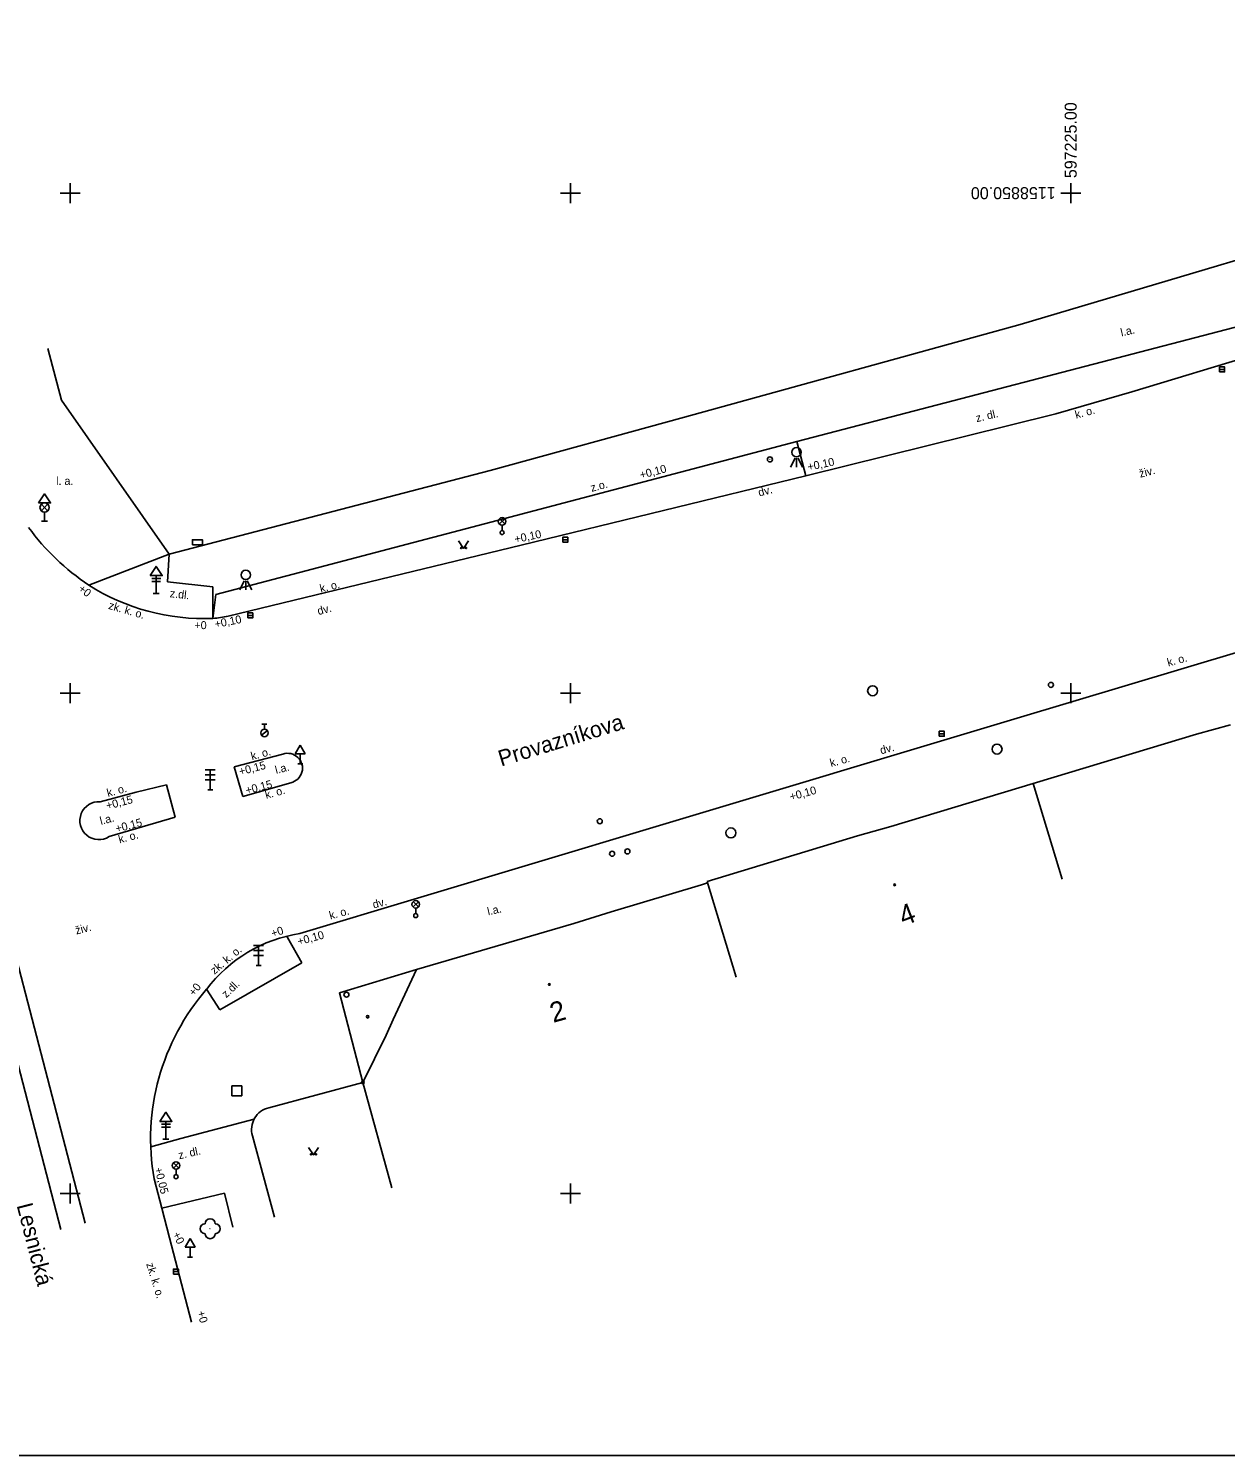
# Model space of a CAD drawing. Extents: x -597333 to -596488, y -1158921 to -1158644.
# Drawn here: x -597277.1 to -597217.3, y -1158913.1 to -1158841.8 of the extents above; entities that cross this region are included whole.
import ezdxf

# ---------------------------------------------------------------- set-up
doc = ezdxf.new("R2010")
doc.units = 0
for name, color, linetype in [('Vrstva 1', 7, 'Continuous'), ('Vrstva 10', 7, 'Continuous'), ('Vrstva 14', 7, 'Continuous'), ('Vrstva 15', 7, 'Continuous'), ('Vrstva 19', 7, 'Continuous'), ('Vrstva 23', 7, 'Continuous'), ('Vrstva 24', 7, 'Continuous'), ('Vrstva 25', 7, 'Continuous'), ('Vrstva 26', 7, 'Continuous'), ('Vrstva 29', 7, 'Continuous'), ('Vrstva 4', 7, 'Continuous'), ('Vrstva 42', 7, 'Continuous'), ('Vrstva 43', 7, 'Continuous'), ('Vrstva 44', 7, 'Continuous'), ('Vrstva 49', 7, 'Continuous'), ('Vrstva 5', 7, 'Continuous'), ('Vrstva 50', 7, 'Continuous'), ('Vrstva 52', 7, 'Continuous'), ('Vrstva 62', 7, 'Continuous'), ('Vrstva 7', 7, 'Continuous')]:
    doc.layers.add(name, color=color, linetype=linetype)

msp = doc.modelspace()

# ---------------------------------------------------------------- linework, layer by layer
at = {"layer": 'Vrstva 1'}
msp.add_lwpolyline([(-597328.148, -1158764.603), (-597328.148, -1158913.103), (-597118.148, -1158913.103), (-597118.148, -1158764.603)], close=True, dxfattribs=at)
at = {"layer": 'Vrstva 10'}
for p, q in [((-597276.111, -1158857.77), (-597275.433, -1158860.345)), ((-597275.433, -1158860.345), (-597270.051, -1158868.049)), ((-597270.051, -1158868.049), (-597254.01, -1158863.867)), ((-597260.372, -1158894.457), (-597265.078, -1158895.721)), ((-597265.889, -1158897.126), (-597264.792, -1158901.192))]:
    msp.add_line(p, q, dxfattribs=at)
for points in [[(-597227.519, -1158856.574), (-597207.014, -1158850.47), (-597187.728, -1158844.729)], [(-597254.01, -1158863.867), (-597244.293, -1158861.192), (-597227.519, -1158856.574)]]:
    msp.add_lwpolyline(points, dxfattribs=at)
msp.add_arc((-597264.82, -1158896.806), 1.116, 103.36333, 196.64751, dxfattribs=at)
at = {"layer": 'Vrstva 14'}
for points in [[(-597255.588, -1158867.388), (-597255.338, -1158867.763), (-597255.088, -1158867.388)], [(-597263.091, -1158897.7), (-597262.841, -1158898.075), (-597262.591, -1158897.7)]]:
    msp.add_lwpolyline(points, dxfattribs=at)
for centre, radius in [((-597255.463, -1158867.738), 0.025), ((-597255.213, -1158867.738), 0.025), ((-597262.966, -1158898.05), 0.025), ((-597262.716, -1158898.05), 0.025), ((-597268.006, -1158901.768), 0.00025)]:
    msp.add_circle(centre, radius, dxfattribs=at)
for centre, start, end in [((-597268.006, -1158901.518), 0, 179.99999), ((-597268.256, -1158901.768), 89.99999, 269.99999), ((-597268.006, -1158902.018), 179.99999, 359.99999), ((-597267.756, -1158901.768), 270, 89.99999)]:
    msp.add_arc(centre, 0.25, start, end, dxfattribs=at)
at = {"layer": 'Vrstva 15'}
for centre, radius in [((-597240.029, -1158863.311), 0.125), ((-597240.029, -1158863.311), 0.00025), ((-597233.796, -1158884.579), 0.0438), ((-597251.054, -1158889.555), 0.0438), ((-597260.136, -1158891.173), 0.0625), ((-597260.136, -1158891.173), 0.0625), ((-597260.372, -1158894.457), 0.0625), ((-597260.372, -1158894.457), 0.0625)]:
    msp.add_circle(centre, radius, dxfattribs=at)
at = {"layer": 'Vrstva 19'}
for p, q in [((-597275.466, -1158901.802), (-597286.662, -1158858.767)), ((-597263.503, -1158877.595), (-597263.753, -1158878.028)), ((-597263.503, -1158877.595), (-597263.253, -1158878.028)), ((-597263.753, -1158878.028), (-597263.253, -1158878.028)), ((-597263.503, -1158878.528), (-597263.503, -1158878.028)), ((-597267.753, -1158878.825), (-597268.253, -1158878.825)), ((-597268.253, -1158879.075), (-597267.753, -1158879.075)), ((-597268.003, -1158879.825), (-597268.003, -1158878.825)), ((-597263.628, -1158878.528), (-597263.378, -1158878.528)), ((-597268.253, -1158879.325), (-597267.753, -1158879.325)), ((-597268.128, -1158879.825), (-597267.878, -1158879.825)), ((-597265.339, -1158887.604), (-597265.839, -1158887.604)), ((-597265.589, -1158888.604), (-597265.589, -1158887.604)), ((-597265.839, -1158887.854), (-597265.339, -1158887.854)), ((-597265.839, -1158888.104), (-597265.339, -1158888.104)), ((-597265.714, -1158888.604), (-597265.464, -1158888.604)), ((-597269.008, -1158902.262), (-597269.258, -1158902.695)), ((-597269.258, -1158902.695), (-597268.758, -1158902.695)), ((-597269.008, -1158902.262), (-597268.758, -1158902.695)), ((-597269.008, -1158903.195), (-597269.008, -1158902.695)), ((-597269.133, -1158903.195), (-597268.883, -1158903.195))]:
    msp.add_line(p, q, dxfattribs=at)
at = {"layer": 'Vrstva 23'}
for p, q in [((-597266.419, -1158894.622), (-597266.919, -1158894.622)), ((-597266.919, -1158894.622), (-597266.919, -1158895.122)), ((-597266.419, -1158895.122), (-597266.419, -1158894.622)), ((-597266.919, -1158895.122), (-597266.419, -1158895.122))]:
    msp.add_line(p, q, dxfattribs=at)
msp.add_circle((-597261.194, -1158890.067), 0.125, dxfattribs=at)
at = {"layer": 'Vrstva 24'}
for p, q in [((-597265.438, -1158877.101), (-597265.143, -1158876.869)), ((-597265.416, -1158876.547), (-597265.166, -1158876.547)), ((-597265.291, -1158876.797), (-597265.291, -1158876.547))]:
    msp.add_line(p, q, dxfattribs=at)
for centre, radius in [((-597225.986, -1158874.582), 0.125), ((-597265.291, -1158876.985), 0.188), ((-597248.533, -1158881.4), 0.125)]:
    msp.add_circle(centre, radius, dxfattribs=at)
at = {"layer": 'Vrstva 25'}
for p, q in [((-597217.561, -1158858.815), (-597217.311, -1158858.815)), ((-597250.386, -1158867.327), (-597250.137, -1158867.326)), ((-597266.123, -1158871.111), (-597265.873, -1158871.111)), ((-597231.567, -1158877.028), (-597231.317, -1158877.028)), ((-597269.839, -1158903.911), (-597269.589, -1158903.911))]:
    msp.add_line(p, q, dxfattribs=at)
for points in [[(-597217.561, -1158858.94), (-597217.311, -1158858.94), (-597217.311, -1158858.69), (-597217.561, -1158858.69)], [(-597250.386, -1158867.453), (-597250.136, -1158867.452), (-597250.137, -1158867.201), (-597250.387, -1158867.202)], [(-597266.123, -1158871.236), (-597265.873, -1158871.236), (-597265.873, -1158870.986), (-597266.123, -1158870.986)], [(-597231.567, -1158877.153), (-597231.317, -1158877.153), (-597231.317, -1158876.903), (-597231.567, -1158876.903)], [(-597269.839, -1158904.036), (-597269.589, -1158904.036), (-597269.589, -1158903.786), (-597269.839, -1158903.786)]]:
    msp.add_lwpolyline(points, close=True, dxfattribs=at)
for centre in [(-597234.897, -1158874.875), (-597228.681, -1158877.793), (-597241.98, -1158881.983)]:
    msp.add_circle(centre, 0.25, dxfattribs=at)
at = {"layer": 'Vrstva 26'}
for centre in [(-597247.915, -1158883.022), (-597247.155, -1158882.907)]:
    msp.add_circle(centre, 0.125, dxfattribs=at)
at = {"layer": 'Vrstva 29'}
for p, q in [((-597253.548, -1158866.537), (-597253.284, -1158866.273)), ((-597253.28, -1158866.536), (-597253.544, -1158866.271)), ((-597253.416, -1158866.868), (-597253.416, -1158866.593)), ((-597257.863, -1158885.684), (-597257.599, -1158885.42)), ((-597257.595, -1158885.683), (-597257.859, -1158885.418)), ((-597257.731, -1158886.015), (-597257.731, -1158885.74)), ((-597269.844, -1158898.739), (-597269.58, -1158898.475)), ((-597269.576, -1158898.738), (-597269.84, -1158898.473)), ((-597269.712, -1158899.07), (-597269.712, -1158898.795))]:
    msp.add_line(p, q, dxfattribs=at)
msp.add_lwpolyline([(-597268.889, -1158867.574), (-597268.389, -1158867.574), (-597268.389, -1158867.324), (-597268.889, -1158867.324)], close=True, dxfattribs=at)
for centre, radius in [((-597253.416, -1158866.406), 0.188), ((-597253.416, -1158866.968), 0.1), ((-597257.731, -1158885.552), 0.188), ((-597257.731, -1158886.115), 0.1), ((-597269.712, -1158898.607), 0.188), ((-597269.712, -1158899.17), 0.1)]:
    msp.add_circle(centre, radius, dxfattribs=at)
at = {"layer": 'Vrstva 4'}
for p, q in [((-597233.98, -1158881.656), (-597218.708, -1158877.038)), ((-597225.433, -1158884.295), (-597226.881, -1158879.509)), ((-597243.166, -1158884.417), (-597235.651, -1158882.131)), ((-597247.96, -1158885.926), (-597243.454, -1158884.577)), ((-597243.145, -1158884.485), (-597243.454, -1158884.577)), ((-597241.711, -1158889.201), (-597243.166, -1158884.417)), ((-597257.696, -1158888.817), (-597249.835, -1158886.508)), ((-597258.854, -1158891.311), (-597257.696, -1158888.817)), ((-597260.372, -1158894.457), (-597259.213, -1158892.094)), ((-597260.372, -1158894.457), (-597258.931, -1158899.728))]:
    msp.add_line(p, q, dxfattribs=at)
msp.add_lwpolyline([(-597257.696, -1158888.817), (-597261.543, -1158889.968), (-597260.372, -1158894.457)], dxfattribs=at)
at = {"layer": 'Vrstva 44'}
for p, q in [((-597238.776, -1158863.242), (-597239.002, -1158863.694)), ((-597238.702, -1158863.244), (-597238.702, -1158863.694)), ((-597238.627, -1158863.242), (-597238.402, -1158863.694)), ((-597276.132, -1158865.542), (-597276.432, -1158865.886)), ((-597276.432, -1158865.542), (-597276.132, -1158865.886)), ((-597276.282, -1158866.392), (-597276.282, -1158865.942)), ((-597276.432, -1158866.392), (-597276.132, -1158866.392)), ((-597270.704, -1158869.113), (-597270.704, -1158870.013)), ((-597270.924, -1158869.263), (-597270.476, -1158869.263)), ((-597270.924, -1158869.413), (-597270.481, -1158869.413)), ((-597266.298, -1158869.379), (-597266.524, -1158869.831)), ((-597266.224, -1158869.381), (-597266.224, -1158869.831)), ((-597266.149, -1158869.379), (-597265.924, -1158869.831)), ((-597270.854, -1158870.013), (-597270.554, -1158870.013)), ((-597270.433, -1158896.549), (-597269.985, -1158896.549)), ((-597270.433, -1158896.699), (-597269.99, -1158896.699)), ((-597270.213, -1158896.399), (-597270.213, -1158897.299)), ((-597270.363, -1158897.299), (-597270.063, -1158897.299))]:
    msp.add_line(p, q, dxfattribs=at)
msp.add_lwpolyline([(-597276.582, -1158865.486), (-597275.982, -1158865.486), (-597276.282, -1158865.036), (-597276.582, -1158865.486)], dxfattribs=at)
for points in [[(-597271.004, -1158869.118), (-597270.704, -1158868.663), (-597270.404, -1158869.118)], [(-597270.513, -1158896.404), (-597270.213, -1158895.949), (-597269.913, -1158896.404)]]:
    msp.add_lwpolyline(points, close=True, dxfattribs=at)
for centre, radius in [((-597238.702, -1158862.949), 0.234), ((-597276.282, -1158865.714), 0.228), ((-597266.224, -1158869.086), 0.234)]:
    msp.add_circle(centre, radius, dxfattribs=at)
at = {"layer": 'Vrstva 5'}
for p, q in [((-597218.708, -1158877.038), (-597217.007, -1158876.583)), ((-597235.651, -1158882.131), (-597233.98, -1158881.656)), ((-597249.835, -1158886.508), (-597247.96, -1158885.926)), ((-597259.213, -1158892.094), (-597258.854, -1158891.311))]:
    msp.add_line(p, q, dxfattribs=at)
at = {"layer": 'Vrstva 62'}
for p, q in [((-597275, -1158849.5), (-597275, -1158850.5)), ((-597250, -1158849.5), (-597250, -1158850.5)), ((-597225, -1158849.5), (-597225, -1158850.5)), ((-597275.5, -1158850), (-597274.5, -1158850)), ((-597250.5, -1158850), (-597249.5, -1158850)), ((-597225.5, -1158850), (-597224.5, -1158850)), ((-597275, -1158874.5), (-597275, -1158875.5)), ((-597250, -1158874.5), (-597250, -1158875.5)), ((-597225, -1158874.5), (-597225, -1158875.5)), ((-597275.5, -1158875), (-597274.5, -1158875)), ((-597250.5, -1158875), (-597249.5, -1158875)), ((-597225.5, -1158875), (-597224.5, -1158875)), ((-597275, -1158899.5), (-597275, -1158900.5)), ((-597250, -1158899.5), (-597250, -1158900.5)), ((-597275.5, -1158900), (-597274.5, -1158900)), ((-597250.5, -1158900), (-597249.5, -1158900))]:
    msp.add_line(p, q, dxfattribs=at)
at = {"layer": 'Vrstva 7'}
for p, q in [((-597221.951, -1158859.927), (-597201.328, -1158853.717)), ((-597238.686, -1158862.421), (-597216.443, -1158856.62)), ((-597274.256, -1158901.487), (-597285.452, -1158858.452)), ((-597225.739, -1158861.027), (-597221.951, -1158859.927)), ((-597228.084, -1158861.62), (-597225.739, -1158861.027)), ((-597238.243, -1158864.124), (-597228.084, -1158861.62)), ((-597253.35, -1158866.285), (-597238.686, -1158862.421)), ((-597238.243, -1158864.124), (-597238.686, -1158862.421)), ((-597252.455, -1158867.597), (-597238.243, -1158864.124)), ((-597267.724, -1158870.062), (-597253.35, -1158866.285)), ((-597267.11, -1158871.153), (-597252.455, -1158867.597)), ((-597274.069, -1158869.593), (-597270.051, -1158868.049)), ((-597270.132, -1158869.425), (-597270.051, -1158868.049)), ((-597270.132, -1158869.425), (-597267.878, -1158869.678)), ((-597267.878, -1158869.678), (-597267.868, -1158871.261)), ((-597267.868, -1158871.261), (-597267.724, -1158870.062)), ((-597266.808, -1158878.672), (-597264.37, -1158878.039)), ((-597266.808, -1158878.672), (-597266.377, -1158880.162)), ((-597270.182, -1158879.58), (-597271.701, -1158879.946)), ((-597270.182, -1158879.58), (-597269.759, -1158881.188)), ((-597266.377, -1158880.162), (-597263.978, -1158879.472)), ((-597273.504, -1158880.421), (-597271.701, -1158879.946)), ((-597269.759, -1158881.188), (-597273.055, -1158882.167)), ((-597264.175, -1158887.146), (-597264.139, -1158887.211)), ((-597263.428, -1158888.48), (-597264.139, -1158887.211)), ((-597267.518, -1158890.825), (-597263.428, -1158888.48)), ((-597268.186, -1158889.801), (-597267.518, -1158890.825)), ((-597265.808, -1158896.288), (-597269.466, -1158897.266)), ((-597270.976, -1158897.669), (-597269.466, -1158897.266)), ((-597270.426, -1158900.741), (-597270.809, -1158899.275)), ((-597270.426, -1158900.741), (-597267.287, -1158899.986)), ((-597267.287, -1158899.986), (-597266.868, -1158901.685)), ((-597270.045, -1158902.227), (-597270.426, -1158900.741)), ((-597268.941, -1158906.441), (-597270.045, -1158902.227))]:
    msp.add_line(p, q, dxfattribs=at)
msp.add_lwpolyline([(-597263.524, -1158887.016), (-597245.881, -1158881.719), (-597227.838, -1158876.302), (-597210.813, -1158871.191), (-597207.322, -1158870.143), (-597204.14, -1158869.11)], dxfattribs=at)
for centre, radius, start, end in [((-597267.49, -1158859.706), 11.876, 216.12799, 236.35866), ((-597268.317, -1158860.57), 10.7, 237.48348, 272.40539), ((-597268.767, -1158862.241), 9.065, 275.68849, 280.52938), ((-597264.136, -1158878.745), 0.744, 282.29044, 108.30774), ((-597273.567, -1158881.368), 0.949, 86.20281, 302.6405), ((-597262.448, -1158894.113), 7.178, 98.62559, 143.08118), ((-597259.546, -1158897.293), 11.436, 139.07067, 189.97845)]:
    msp.add_arc(centre, radius, start, end, dxfattribs=at)

# ---------------------------------------------------------------- texts
at = {"layer": 'Vrstva 42'}
for s, rotation, p in [('Provazníkova', 17, (-597253.465, -1158878.665)), ('Lesnická', 284.48073, (-597277.682, -1158900.598))]:
    msp.add_text(s, height=0.8, rotation=rotation, dxfattribs=at).set_placement(p)
at = {"layer": 'Vrstva 43'}
for s, rotation, p in [('4', 20.83848, (-597233.354, -1158886.644)), ('2', 15.87366, (-597250.862, -1158891.482))]:
    msp.add_text(s, height=1, rotation=rotation, dxfattribs=at).set_placement(p)
at = {"layer": 'Vrstva 49'}
for s, rotation, p in [('l.a.', 12.80009, (-597222.459, -1158857.164)), ('z. dl.', 13.10126, (-597229.693, -1158861.448)), ('k. o.', 15, (-597224.727, -1158861.276)), ('živ.', 14.62948, (-597221.52, -1158864.227)), ('z.o.', 15, (-597248.936, -1158864.934)), ('dv.', 15, (-597240.559, -1158865.17)), ('z.dl.', 353.59565, (-597270.037, -1158870.194)), ('k. o.', 13.63908, (-597262.475, -1158869.966)), ('zk. k. o.', 343.98032, (-597273.118, -1158870.776)), ('dv.', 15, (-597262.591, -1158871.096)), ('k. o.', 15, (-597220.121, -1158873.663)), ('dv.', 15, (-597234.47, -1158878.056)), ('k. o.', 15, (-597265.914, -1158878.348)), ('k. o.', 15, (-597236.976, -1158878.686)), ('l.a.', 14.78065, (-597264.703, -1158879.039)), ('k. o.', 15, (-597273.113, -1158880.184)), ('k. o.', 15, (-597265.203, -1158880.282)), ('l.a.', 14.78065, (-597273.46, -1158881.585)), ('k. o.', 15, (-597272.531, -1158882.507)), ('dv.', 15, (-597259.829, -1158885.766)), ('k. o.', 15, (-597261.997, -1158886.311)), ('l.a.', 12.80009, (-597254.107, -1158886.107)), ('živ.', 14.62948, (-597274.687, -1158887.064)), ('zk. k. o.', 40.30439, (-597267.789, -1158889.076)), ('z.dl.', 43.70794, (-597267.203, -1158890.254)), ('z. dl.', 12.73831, (-597269.548, -1158898.298)), ('zk. k. o.', 287.20912, (-597271.207, -1158903.531))]:
    msp.add_text(s, height=0.4, rotation=rotation, dxfattribs=at).set_placement(p)
msp.add_text('l. a.', height=0.4, dxfattribs=at).set_placement((-597275.703, -1158864.585))
at = {"layer": 'Vrstva 50'}
for s, rotation, p in [('+0,10', 11.7972, (-597238.108, -1158863.883)), ('+0,10', 14.6923, (-597246.479, -1158864.288)), ('+0,10', 11.7972, (-597252.752, -1158867.496)), ('+0', 321.69494, (-597274.629, -1158869.839)), ('+0,10', 11.16984, (-597267.74, -1158871.742)), ('+0,15', 14.62363, (-597266.506, -1158879.112)), ('+0,15', 14.62363, (-597266.18, -1158880.058)), ('+0,10', 15.3599, (-597238.982, -1158880.374)), ('+0,15', 14.62363, (-597273.148, -1158880.822)), ('+0,15', 14.62363, (-597272.681, -1158881.97)), ('+0', 18.44414, (-597264.882, -1158887.21)), ('+0,10', 15.3599, (-597263.584, -1158887.608)), ('+0', 52.36719, (-597268.802, -1158890.169)), ('+0,05', 284.24025, (-597270.794, -1158898.753)), ('+0', 296.40893, (-597269.898, -1158902.038)), ('+0', 285.74354, (-597268.662, -1158905.929))]:
    msp.add_text(s, height=0.4, rotation=rotation, dxfattribs=at).set_placement(p)
msp.add_text('+0', height=0.4, dxfattribs=at).set_placement((-597268.791, -1158871.795))
at = {"layer": 'Vrstva 52'}
for s, rotation, p in [('597225.00', 90, (-597224.7, -1158849.25)), ('1158850.00', 180, (-597225.75, -1158849.7))]:
    msp.add_text(s, height=0.6, rotation=rotation, dxfattribs=at).set_placement(p)

doc.saveas('drawing.dxf')
